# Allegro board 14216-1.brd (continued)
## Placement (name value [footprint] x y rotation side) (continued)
C8006  SC1U6D3V3KX-2GP  [C603H36]  200.97 141.05 90 top
C8007  SC1U6D3V3KX-2GP  [C603H36]  200.9 139.79 270 bottom
C8008  SC1U6D3V3KX-2GP  [C603H36]  200.93 151.95 90 top
C8009  SC1U6D3V3KX-2GP  [C603H36]  200.94 150.6 90 top
C8010  SCD1U16V2KX-3GP  [C402H22]  201.13 136.6 270 bottom
C8011  SCD1U16V2KX-3GP  [C402H22]  169.76 174.17 0 bottom
C8012  SCD1U16V2KX-3GP  [C402H22]  200.93 152.44 270 bottom
C8013  SCD1U16V2KX-3GP  [C402H22]  151.75 165.94 90 bottom
C8014  SC1U6D3V3KX-2GP  [C603H36]  200.94 147.92 90 top
C8015  SC1U6D3V3KX-2GP  [C603H36]  200.97 142.39 90 top
C8016  SC1U6D3V3KX-2GP  [C603H36]  200.94 153.29 90 top
C8017  SCD1U16V2KX-3GP  [C402H22]  183.12 143.86 270 bottom
C8018  SCD1U16V2KX-3GP  [C402H22]  158.24 173.13 0 bottom
C8019  SCD1U16V2KX-3GP  [C402H22]  188.26 143.87 90 bottom
C8020  SCD1U16V2KX-3GP  [C402H22]  198.28 140.52 90 bottom
C8101  SCD1U16V2KX-3GP  [C402H22]  185.94 173.4 180 top
C8102  SCD1U16V2KX-3GP  [C402H22]  180.83 169.8 270 bottom
C8103  SC1U6D3V3KX-2GP  [C603H36]  157.1 172.57 180 top
C8104  SCD1U16V2KX-3GP  [C402H22]  166.22 157.08 0 top
C8105  SCD1U16V2KX-3GP  [C402H22]  174.71 174.1 0 bottom
C8106  SC1U6D3V3KX-2GP  [C603H36]  188.33 173.83 180 top
C8107  SC1U6D3V3KX-2GP  [C603H36]  189.62 173.84 180 top
C8108  SC1U6D3V3KX-2GP  [C603H36]  175.04 173.62 180 top
C8109  SC1U6D3V3KX-2GP  [C603H36]  184.04 173.61 180 top
C8110  SCD1U16V2KX-3GP  [C402H22]  151.62 169.98 270 top
C8111  SCD1U16V2KX-3GP  [C402H22]  166.22 158.75 180 top
C8112  SCD1U16V2KX-3GP  [C402H22]  177.52 173.66 180 top
C8113  SCD1U16V2KX-3GP  [C402H22]  155.52 173.13 0 bottom
C8114  SC1U6D3V3KX-2GP  [C603H36]  176.42 173.63 180 top
C8115  SC1U6D3V3KX-2GP  [C603H36]  155.78 172.57 180 top
C8116  SC1U6D3V3KX-2GP  [C603H36]  151.52 162.06 90 bottom
C8117  SCD1U16V2KX-3GP  [C402H22]  176.61 174.15 0 bottom
C8118  SCD1U16V2KX-3GP  [C402H22]  151.78 169.61 90 bottom
C8119  SCD1U16V2KX-3GP  [C402H22]  151.77 170.46 90 bottom
C8120  SCD1U16V2KX-3GP  [C402H22]  180.85 171.08 270 bottom
C8301  SCD01U50V2KX-1GP  [C402H22]  142.67 133.14 270 top
C8302  SC1U10V2KX-1GP  [C402H22]  146.16 140.24 180 top
C8303  SCD1U16V2KX-3GP  [C402H22]  144.58 137.75 270 bottom
C8304  SC1U10V2KX-1GP  [C402H22]  146.67 134.78 90 top
C8305  SC470P50V2KX-3GP  [C402H22]  148.83 136.94 90 bottom
C8306  SCD1U16V2KX-3GP  [C402H22]  151.24 148.48 180 bottom
C8307  SC10U10V5KX-2GP  [C805H54]  147.81 132.62 270 top
C8308  SCD1U16V2KX-3GP  [C402H22]  149.75 134.08 90 top
C8309  SCD1U16V2KX-3GP  [C402H22]  144.22 138.24 0 top
C8310  SC10U10V5KX-2GP  [C805H54]  148.19 140.36 270 top
C8311  SCD1U16V2KX-3GP  [C402H22]  146.24 133.94 90 top
C8316  SC2200P50V2KX-2GP  [C402H22]  148.83 137.82 90 bottom
C9602  SCD1U16V2KX-3GP  [C402H22]  166.48 86.68 270 top
CARD1  CARDBUS11P-SKT-8-GP  [CS1S-461HN]  22.1 16.87 270 top
CN6301  PTWO-CON24-7-GP  [196547-24031-3]  194.45 33.27 90 top
CPU1  HASWELL-6-GP-U  [BGA1168M4024H64]  117.8 83.77 0 bottom
D2001  RB751V-40H-GP  [SOD323AKH38]  149.02 80.12 270 top
D2401  RB751V-40-H-GP  [SOD323AKH40]  188.2 67.11 90 bottom
D2501  BAS40C-2-GP  [SOT-23-9H44]  30.14 11.71 90 top
D2601  RB551V30-GP  [SOD323AKH38]  100.29 141.48 90 bottom
D2701  BAT54C-7-F-3-GP  [SOT23-2D4-312H48]  174.32 24.68 0 bottom
D3602  BAS16-6-GP  [SOT23-2D4-312H44]  164.95 63.3 270 top
D4301  LBAV99LT1G-1-GP  [SOT23-2D4-312H44]  187.65 177.88 0 top
D4302  LBAV99LT1G-1-GP  [SOT23-2D4-312H44]  174.76 177.72 0 top
D4303  LBAV99LT1G-1-GP  [SOT23-2D4-312H44]  183.66 177.88 0 top
D5201  BAT54C-7-F-3-GP  [SOT23-2D4-312H48]  69.17 161.68 270 bottom
D5202  BAT54C-7-F-3-GP  [SOT23-2D4-312H48]  61.56 165.37 0 top
D5401  BAW56-5-GP  [SOT-23-9H44]  40.55 79.02 90 bottom
D5501  RB551V30-GP  [SOD323AKH38]  31.91 70.36 270 top
D7301  BAT54A-1-GP  [SOT23-2D4-312H44]  154.66 124.41 180 bottom
D7601  1SS400GPT-GP  [SOD723AKH27]  172.45 127.41 270 top
D7602  1SS400GPT-GP  [SOD723AKH27]  172.45 126.13 270 top
D8301  BAT54C-7-F-3-GP  [SOT23-2D4-312H48]  167.61 53.76 90 top
DB1  PAD-10P-177042-GP  [PAD-10P-177042]  170.29 30.76 180 bottom
DCIN1  ACES-CON6-63-GP  [50458-00601-W01]  92.8 166.77 180 top
DM1  DDR3-204P-108-GP-U  [80001-1921]  92.3 34.07 180 bottom
DM2  DDR3-204P-259-GP  [AS0A621-J4SB-7H]  126.8 20.87 0 bottom
EC401  SCD1U16V2KX-3GP  [C402H22]  92.88 97.78 90 bottom
EC402  SCD1U16V2KX-3GP  [C402H22]  101.2 94.14 180 top
EC701  SCD1U16V2KX-3GP  [C402H22]  97.58 100.22 90 bottom
EC702  SCD1U16V2KX-3GP  [C402H22]  95.68 99.36 90 bottom
EC1501  SC1KP50V2KX-1GP  [C402H22]  144.39 100.83 90 top
EC1502  SC1KP50V2KX-1GP  [C402H22]  149.87 91.3 270 bottom
EC1701  SC4D7P50V2BN-GP  [C402H22]  150.73 84.61 90 bottom
EC1702  SC1KP50V2KX-1GP  [C402H22]  171.04 83.6 270 bottom
EC1703  SC1KP50V2KX-1GP  [C402H22]  149.83 93.02 90 bottom
EC1704  SC1KP50V2KX-1GP  [C402H22]  139.26 55.99 0 bottom
EC1705  SC1KP50V2KX-1GP  [C402H22]  143.01 52.79 270 bottom
EC1706  SC1KP50V2KX-1GP  [C402H22]  166.48 85.8 270 top
EC1707  SCD1U16V2KX-3GP  [C402H22]  168.77 80.5 90 top
EC1801  SC10P50V2JN-4GP  [C402H22]  127.97 62.67 0 top
EC1901  SC10P50V2JN-4GP  [C402H22]  138.42 62.69 0 bottom
EC1902  SCD1U16V2KX-3GP  [C402H22]  139.24 62.69 180 bottom
EC1903  SCD1U16V2KX-3GP  [C402H22]  143.82 62.69 0 top
EC2501  SC4D7P50V2BN-GP  [C402H22]  145.93 52.36 180 bottom
EC2502  SC4D7P50V2BN-GP  [C402H22]  157.41 51.62 180 bottom
EC2503  SC10P50V2JN-4GP  [C402H22]  145.93 54.14 0 bottom
EC2601  SCD1U16V2KX-3GP  [C402H22]  100.03 137.67 270 bottom
EC2602  SC10P50V2JN-4GP  [C402H22]  96.15 141.03 90 bottom
EC2701  SC10P50V2JN-4GP  [C402H22]  177.3 12.4 90 bottom
EC2703  SCD1U25V2KX-GP  [C402H22]  185.61 7.94 90 bottom
EC2704  SC1KP50V2KX-1GP  [C402H22]  189.9 12.39 90 bottom
EC2705  SC1KP50V2KX-1GP  [C402H22]  189.47 9.55 180 bottom
EC2706  SC1KP50V2KX-1GP  [C402H22]  192.26 14.56 270 bottom
EC2707  SC1KP50V2KX-1GP  [C402H22]  190.43 9.58 180 bottom
EC2708  SCD1U16V2KX-3GP  [C402H22]  174.66 15.53 90 bottom
EC2709  SCD1U16V2KX-3GP  [C402H22]  175.68 16.34 90 bottom
EC2901  SC1KP50V2KX-1GP  [C402H22]  90.64 4.68 0 top
EC2902  SC1KP50V2KX-1GP  [C402H22]  91.76 7.07 180 top
EC2903  SC1KP50V2KX-1GP  [C402H22]  90.38 8.31 0 top
EC2904  SC1KP50V2KX-1GP  [C402H22]  90.43 11.28 180 top
EC2905  SC100P50V2JN-3GP  [C402H22]  182.1 23.4 90 bottom
EC2906  SC100P50V2JN-3GP  [C402H22]  183.88 23.4 270 bottom
EC2907  SC100P50V2JN-3GP  [C402H22]  192.13 16.41 270 bottom
EC2908  SC100P50V2JN-3GP  [C402H22]  181.39 27 180 top
EC3101  SC10P50V2JN-4GP  [C402H22]  39.35 171.62 0 bottom
EC3102  SC10P50V2JN-4GP  [C402H22]  39.35 173.4 180 bottom
EC3103  SC10P50V2JN-4GP  [C402H22]  39.35 175.1 0 bottom
EC3104  SC10P50V2JN-4GP  [C402H22]  39.35 176.88 180 bottom
EC3105  SC10P50V2JN-4GP  [C402H22]  39.35 171.62 180 top
EC3106  SC10P50V2JN-4GP  [C402H22]  39.35 173.4 0 top
EC3107  SC10P50V2JN-4GP  [C402H22]  39.35 175.1 180 top
EC3108  SC10P50V2JN-4GP  [C402H22]  39.35 176.88 0 top
EC3201  SC10P50V2JN-4GP  [C402H22]  29.6 21.14 90 top
EC3301  SC4D7P50V2BN-GP  [C402H22]  29.52 24.87 90 top
EC3302  SC4D7P50V2BN-GP  [C402H22]  30.06 14.12 90 top
EC3303  SC4D7P50V2BN-GP  [C402H22]  29.99 15.22 90 top
EC3304  SC4D7P50V2BN-GP  [C402H22]  29.95 16.34 90 top
EC3305  SC4D7P50V2BN-GP  [C402H22]  29.57 27.16 90 top
EC3306  SC4D7P50V2BN-GP  [C402H22]  29.59 23.49 90 top
EC3307  SC4D7P50V2BN-GP  [C402H22]  29.57 28.6 90 top
EC4201  SC10U25V5KX-GP  [C805H56]  92.67 159.64 90 top
EC4202  SCD1U25V2KX-GP  [C402H22]  92.54 158.25 90 top
EC4301  SC10P50V2JN-4GP  [C402H22]  186.55 175.38 90 top
EC4302  SC10P50V2JN-4GP  [C402H22]  184.74 175.37 270 top
EC4303  SCD1U25V2KX-GP  [C402H22]  152.17 173.1 0 top
EC4304  SCD1U50V3KX-GP  [C603H36]  151.03 173.18 0 top
EC4305  SC15P50V2JN-2-GP  [C402H22]  176.05 175.27 270 top
EC4401  SC2200P50V2KX-2GP  [C402H22]  120.3 159.59 180 top
EC4402  SCD1U25V2KX-GP  [C402H22]  120.3 159.59 0 bottom
EC4601  SCD1U50V3KX-GP  [C603H36]  78.71 16.88 0 top
EC4701  SCD1U25V2KX-GP  [C402H22]  103.18 104.6 90 bottom
EC5205  SC6D8P50V2DN-GP  [C402H22]  82.15 166.72 180 top
EC5206  SC22P50V2JN-4GP  [C402H22]  81.29 166.73 180 top
EC5210  SC33P50V2JN-3GP  [C402H22]  82.86 158.65 180 bottom
EC5801  SC33P50V2JN-3GP  [C402H22]  168.16 65.77 270 bottom
EC5802  SC33P50V2JN-3GP  [C402H22]  166.41 65.76 90 bottom
EC6101  SC1KP50V2KX-1GP  [C402H22]  191.19 174.19 270 top
EC6102  SC220P50V2KX-3GP  [C402H22]  31.9 4.56 90 top
EC6103  SC220P50V2KX-3GP  [C402H22]  35.72 4.54 90 top
EC6104  SCD1U16V2KX-3GP  [C402H22]  39.55 3.73 90 top
EC6105  SCD1U16V2KX-3GP  [C402H22]  191.15 177.61 270 top
EC6201  SC33P50V2JN-3GP  [C402H22]  54.67 78.63 180 top
EC6202  SC33P50V2JN-3GP  [C402H22]  54.67 76.86 0 top
EC6203  SC33P50V2JN-3GP  [C402H22]  51.68 72.42 90 top
EC6204  SC33P50V2JN-3GP  [C402H22]  49.99 72.42 270 top
EC6205  SC33P50V2JN-3GP  [C402H22]  46.08 73.4 0 top
EC6206  SC33P50V2JN-3GP  [C402H22]  46.08 75.18 180 top
EC6207  SCD1U16V2KX-3GP  [C402H22]  190.01 125.99 180 top
EC6208  SCD1U16V2KX-3GP  [C402H22]  188.7 122.38 180 top
EC9701  SCD1U25V2KX-GP  [C402H22]  86.01 85.7 90 top
EC9702  SC1KP50V2KX-1GP  [C402H22]  113.91 153.28 0 bottom
EC9703  SCD1U25V2KX-GP  [C402H22]  64.94 64.96 180 top
EC9704  SCD1U25V2KX-GP  [C402H22]  137.8 155.4 90 top
EC9705  SCD1U25V2KX-GP  [C402H22]  57.12 56.64 0 top
EC9706  SCD1U25V2KX-GP  [C402H22]  54.21 32.67 270 top
EC9707  SCD1U25V2KX-GP  [C402H22]  110.73 129.82 180 bottom
EC9708  SC1KP50V2KX-1GP  [C402H22]  121.84 148.31 0 top
EC9709  SC1KP50V2KX-1GP  [C402H22]  33.27 55.49 270 bottom
EC9710  SC1KP50V2KX-1GP  [C402H22]  123.73 146.41 180 bottom
EC9711  SC1KP50V2KX-1GP  [C402H22]  102.07 135.34 90 bottom
EC9712  SCD1U25V2KX-GP  [C402H22]  141.87 148.36 90 top
EC9713  SCD1U25V2KX-GP  [C402H22]  68.82 27.06 90 top
EC9714  SC1KP50V2KX-1GP  [C402H22]  137.78 155.06 270 bottom
EC9715  SC1KP50V2KX-1GP  [C402H22]  141.11 121.46 270 top
EC9716  SC1KP50V2KX-1GP  [C402H22]  135.68 127.85 270 top
EC9717  SC1KP50V2KX-1GP  [C402H22]  154.92 113.64 90 top
EC9718  SC1U10V2KX-1GP  [C402H22]  20.94 32.82 180 bottom
EC9719  SC1U10V2KX-1GP  [C402H22]  196.97 17.69 270 top
EC9720  SC1U10V2KX-1GP  [C402H22]  197.72 38.54 180 bottom
EC9721  SC1U10V2KX-1GP  [C402H22]  44.25 16.51 180 top
EC9722  SC1U10V2KX-1GP  [C402H22]  174.83 8.26 180 bottom
EC9723  SC1U10V2KX-1GP  [C402H22]  73.13 157.81 90 bottom
EC9724  SC1U10V2KX-1GP  [C402H22]  35.05 70.16 90 top
EC9725  SC1U10V2KX-1GP  [C402H22]  196.25 129.99 270 top
EC9726  SC1U10V2KX-1GP  [C402H22]  191.64 55.17 180 top
EC9727  SC1U10V2KX-1GP  [C402H22]  156.17 38.03 0 top
EC9728  SC1U10V2KX-1GP  [C402H22]  201.29 146.85 90 top
EC9729  SC1U10V2KX-1GP  [C402H22]  154.67 172.72 180 top
EC9730  SC1U10V2KX-1GP  [C402H22]  152.16 161.95 180 top
EC9731  SC1U10V2KX-1GP  [C402H22]  181.59 173.79 180 top
EC9732  SC1U10V2KX-1GP  [C402H22]  193.66 7.79 0 bottom
EC9733  SC1U10V2KX-1GP  [C402H22]  61.2 10.42 90 bottom
EC9734  SC1U10V2KX-1GP  [C402H22]  45.2 18.5 0 top
EC9735  SC1U10V2KX-1GP  [C402H22]  60.18 66.83 270 top
EC9736  SC1U10V2KX-1GP  [C402H22]  60.23 66.8 90 bottom
EC9737  SC1U10V2KX-1GP  [C402H22]  38.23 13.01 90 top
EC9738  SC1U10V2KX-1GP  [C402H22]  87.61 152.15 270 bottom
EC9739  SC1KP50V2KX-1GP  [C402H22]  188.75 14.05 0 top
EC9740  SC1KP50V2KX-1GP  [C402H22]  109.51 140.24 270 bottom
EC9741  SC1KP50V2KX-1GP  [C402H22]  162.89 91.68 90 top
EC9742  SCD1U25V2KX-GP  [C402H22]  156.8 117.21 270 bottom
EC9743  SC1KP50V2KX-1GP  [C402H22]  178.71 26.1 90 bottom
EC9744  SC1KP50V2KX-1GP  [C402H22]  179.99 19.81 270 top
EC9745  SC1KP50V2KX-1GP  [C402H22]  184.51 13.77 180 top
EC9746  SCD1U25V2KX-GP  [C402H22]  201.04 134.12 270 bottom
EC9747  SC1KP50V2KX-1GP  [C402H22]  121.14 146.21 180 bottom
EC9748  SC1KP50V2KX-1GP  [C402H22]  99.93 105.44 90 top
EC9749  SCD1U25V2KX-GP  [C402H22]  144.64 127.59 270 top
EC9750  SCD1U25V2KX-GP  [C402H22]  201.02 135.03 270 bottom
EC9751  SCD1U25V2KX-GP  [C402H22]  194.01 84.71 90 bottom
EC9752  SCD1U25V2KX-GP  [C402H22]  193.06 90.5 90 bottom
EC9753  SCD1U25V2KX-GP  [C402H22]  193.43 89.59 90 bottom
EC9754  SCD1U25V2KX-GP  [C402H22]  201.05 133.23 270 bottom
EC9755  SCD1U25V2KX-GP  [C402H22]  178.02 121.71 90 bottom
EC9756  SCD1U25V2KX-GP  [C402H22]  180.04 119.8 90 bottom
EC9757  SCD1U25V2KX-GP  [C402H22]  163.22 121.66 180 bottom
EC9758  SCD1U25V2KX-GP  [C402H22]  168.16 175.1 270 bottom
EC9759  SCD1U25V2KX-GP  [C402H22]  148.94 172.4 180 bottom
EC9760  SCD1U25V2KX-GP  [C402H22]  141.78 178.34 0 bottom
EC9761  SCD1U25V2KX-GP  [C402H22]  134.43 173.06 90 bottom
ED6101  AZ5725-01FDR7G-GP  [SOD882-10D6-1H20]  191.16 175.07 270 top
EL4201  0R0805-PAD-1-GP-U  [0R0805-PAD-U]  92.56 156.47 90 top
EL4202  0R0805-PAD-1-GP-U  [0R0805-PAD-U]  92.55 154.53 90 top
EL4203  0R0805-PAD-1-GP-U  [0R0805-PAD-U]  100.7 159.03 90 top
EL4204  0R0805-PAD-1-GP-U  [0R0805-PAD-U]  100.67 160.88 90 top
EU401  ESD105-B1-02EL-GP  [TVS10D6-D3D5-1H13]  131.3 62.39 90 bottom
EU3101  TVWDF1004AD0-1-GP  [DFN10G2510H26]  37.21 174.12 270 bottom
EU3102  TVWDF1004AD0-1-GP  [DFN10G2510H26]  37.21 174.12 270 top
EU3403  AZC099-04S-1-GP  [SOT-6H58]  20.72 38.07 270 top
EU3404  AZC099-04S-1-GP  [SOT-6H58]  187.87 39.42 270 bottom
EU5602  AZ1045-04F-R7G-GP  [DFN10G2510H26]  185.4 33.63 270 bottom
F5201  POLYSW-1D1A24V-2-GP  [POLYSW-4633-UH63]  95.94 151.44 90 bottom
F5203  POLYSW-D5A6V-1-GP  [POLYSW-2114H50]  73.51 161.19 0 bottom
F5501  POLYSW-1D1A6V-9-GP-U  [POLYSW-2114H30]  20.73 69.86 90 top
F6201  POLYSW-D5A6V-1-GP  [POLYSW-2114H50]  187.3 122.94 90 bottom
FAN1  ETY-CON3-8-GP  [3703K-Q03N-11L]  91.38 140.62 24.9 bottom
FAN261  AP2113MTR-G1-GP  [SOIC8H69]  100.13 145.61 90 bottom
G1901  GAP-OPEN  [CON2O-U]  145.85 61.7 270 bottom
G6101  GAP-OPEN  [CON2O-U]  192.96 173.32 0 top
G6102  GAP-OPEN  [CON2O-U]  191.02 175.85 180 bottom
GPU1  N14M-GE-S-A2-GP  [BGA595M23H83]  166.15 140.17 90 bottom
H1  HOLE256R126-1-GP  [HOLE256R126]  141.7 165.77 0 top
H2  HOLE335R115-GP  [HOLE335R115]  169.3 12.77 0 top
H3  HOLE335R115-GP  [HOLE335R115]  20.3 50.77 0 top
H4  HOLE335R115-GP  [HOLE335R115]  96.3 128.47 0 top
H5  HOLE335R115-GP  [HOLE335R115]  37.4 164.77 0 top
H6  HOLE256R126-1-GP  [HOLE256R126]  199.5 56.27 0 top
H7  HOLE296R182-GP  [HOLE296R182]  153.9 60.97 0 top
HCPU1  HOLE197R166-1-GP  [HOLE197R166]  90.6 70.77 0 top
HCPU2  HOLE197R166-1-GP  [HOLE197R166]  145 70.77 0 top
HCPU3  HOLE197R166-1-GP  [HOLE197R166]  117.8 102.77 0 top
HDA27  ALC3234-CG-GP  [QFN48J6-G465H40]  183.22 16.29 270 bottom
HDD1  STAR-CON12-1-GP  [132F12-010000-A2-R]  194.3 30.88 270 bottom
HDLED1  LED-W-27-GP-U  [LED3015-1A2K-3PH44]  22.7 1.47 90 top
HDMI1  PAD-D-SUB-HDMI-COLAY-GP-U  [PAD-D-SUB-HDMI-COLAY-U]  4.15 65.22 90 bottom
HGPU1  STF237R117H81-1-GP  [STF237R117H81]  149.2 157.37 0 bottom
HGPU2  STF237R117H81-1-GP  [STF237R117H81]  200.9 114.27 0 bottom
HGPU3  STF237R117H81-1-GP  [STF237R117H81]  200.5 158.67 180 bottom
KB1  ACES-CON30-10-GP  [FL4S030HT6R300-DT]  186.85 104.55 270 top
KB_BL1  ACES-CON4-56-GP-U  [51575-00401-W01]  196.2 123.07 90 top
KBC24  NPCE285PA0DX-GP  [LQFP128H63]  185 74.99 270 top
L1101  0R3J-0-U-GP  [R603H22]  132.27 106.52 90 bottom
L1102  0R3J-0-U-GP  [R603H22]  135.13 106.59 270 bottom
L1103  IND-2D2UH-196-GP  [L603H40]  131.74 106.57 0 top
L1104  IND-2D2UH-196-GP  [L603H40]  130.38 106.34 0 top
L3001  IND-4D7UH-242-GP  [L2520-D820H41]  53.21 174.73 180 top
L5501  BLM18BB220SN-GP  [L1608-UH38]  21.15 61.9 270 top
L5502  BLM18BB220SN-GP  [L1608-UH38]  21.2 64.05 270 top
L5503  BLM18BB220SN-GP  [L1608-UH38]  21.09 59.18 270 top
L7301  MHC1608S121PBP-GP  [L603H38]  160 139.08 0 top
L7501  MHC1608S300QBP-GP  [L603H38]  161.39 144.56 270 top
L7601  MHC1608S300QBP-GP  [L603H38]  170.14 129.65 180 top
L7602  MCB1608S181FBP-GP  [L603H38]  168.26 129.7 270 top
LCD1  ACES-CON40-18-GP  [51540-04001-W01]  75.3 167.07 270 top
LED1  LED-OW-8-GP  [LED3020-3P-6H44]  17.7 1.77 180 top
LOM30  RTL8111G-CGT-1-GP-U2  [QFN32J4-G2D85H36]  48.93 168.97 90 top
NOREF  -  [unnamed]  203.92 74.02 0 top
NOREF#2  -  [unnamed]  3.34 7.58 0 top
NOREF#3  -  [#2]  -49.22 -5.53 0 top
NOREF#4  -  [#2]  4.3 -48.23 0 top
NOREF#5  -  [#2]  110.42 56.77 0 top
NOREF#6  *  [unnamed]  71.51 28.5 0 top
NOREF#7  *  [unnamed]  200.9 50.96 0 top
NOREF#8  -  [#2]  196.3 5.01 0 top
NOREF#9  -  [#2]  2.65 126.01 90 top
NOREF#10  -  [#2]  4.3 -48.23 0 top
NOREF#11  *  [unnamed]  169.68 86.67 0 top
NOREF#12  -  [#2]  149.46 10.32 0 top
NOREF#13  *  [unnamed]  4.03 2.99 0 top
NOREF#14  *  [unnamed]  201.01 4.74 0 top
NOREF#15  *  [unnamed]  33.48 177.12 0 top
NOREF#16  -  [unnamed]  -3.72 178.69 0 top
NOREF#17  -  [unnamed]  205.45 184.19 0 top
NOREF#18  *  [unnamed]  0.5 156.41 0 top
NOREF#19  -  [#2]  -8.05 133.14 0 top
NOREF#20  -  [unnamed]  80.02 122.56 0 top
NOREF#21  -  [unnamed]  5.79 79.07 270 top
NOREF#22  *  [unnamed]  201.78 176.85 0 top
NOREF#23  -  [unnamed]  206 4.12 0 top
NOREF#24  -  [unnamed]  148.1 163.97 0 top
NOREF#25  *  [unnamed]  43.72 11.28 0 top
NOREF#26  -  [unnamed]  0.11 16.95 0 top
NOREF#27  -  [#2]  125.19 190.37 180 top
NOREF#28  -  [unnamed]  111.85 187.26 0 top
NOREF#29  *  [unnamed]  15.62 79.19 0 top
NOREF#30  -  [#2]  4.3 -48.23 0 top
NOREF#31  *  [unnamed]  200.4 184.34 0 top
NOREF#32  *  [unnamed]  201.78 176.85 180 bottom
NOREF#33  -  [#2]  125.19 190.37 0 bottom
NOREF#34  *  [unnamed]  150.44 119.23 180 bottom
NOREF#35  *  [unnamed]  200.4 184.34 180 bottom
NOREF#36  *  [unnamed]  201.01 4.74 180 bottom
NOREF#37  *  [unnamed]  0.5 156.41 180 bottom
NOREF#38  *  [unnamed]  150.71 45.57 180 bottom
NOREF#39  *  [unnamed]  15.62 79.19 180 bottom
NOREF#40  *  [unnamed]  4.03 2.99 180 bottom
NOREF#41  -  [#2]  107 0 180 bottom
NOREF#42  -  [#2]  2.65 140.49 270 bottom
NOREF#43  -  [#2]  77.99 71.92 180 bottom
NOREF#44  -  [#2]  196.72 177.44 180 bottom
NOREF#45  -  [#2]  33.99 96.98 180 bottom
ODD1  ACES-CON20-30-GP-U  [51519-02001-W03]  159.3 81.32 90 top
PC4010  SCD47U25V3KX-1GP  [C603H36]  113.49 158.45 180 bottom
PC4201  SC1U25V3KX-1-GP  [C603H36]  96.12 150.02 90 top
PC4202  SCD1U50V3KX-GP  [C603H36]  117.38 176.07 90 top
PC4203  SCD01U50V2KX-1GP  [C402H22]  104.2 153.37 90 top
PC4204  SCD01U50V2KX-1GP  [C402H22]  104.2 155.15 90 top
PC4205  SCD01U50V2KX-1GP  [C402H22]  104.2 154.26 90 top
PC4206  SC10U25V5KX-GP  [C805H56]  104.86 156.65 90 top
PC4401  SC560P50V-GP  [C603]  122.62 160.56 270 top
PC4402  SCD1U25V2KX-GP  [C402H22]  110.1 156.51 90 top
PC4403  SC1U25V3KX-1-GP  [C603H36]  111.37 157.58 90 top
PC4404  SC1U25V3KX-1-GP  [C603H36]  108.96 157.58 270 top
PC4406  SC10U25V5KX-GP  [C805H56]  117.51 159.59 0 bottom
PC4407  SC1U25V3KX-1-GP  [C603H36]  115.78 162.56 0 bottom
PC4408  SC4D7U25V5KX-GP  [C805H54]  118.9 159.59 180 top
PC4409  SCD1U50V3KX-GP  [C603H36]  119.18 159.59 0 bottom
PC4411  SCD047U25V2KX-GP  [C402H22]  111.82 159.91 90 top
PC4412  SCD01U50V2KX-1GP  [C402H22]  107.96 160.61 90 top
PC4413  SC3300P50V3KX-1GP  [C603H36]  114.18 161.37 180 top
PC4415  SC10U25V5KX-GP  [C805H56]  133.15 168.46 270 top
PC4416  SC10U25V5KX-GP  [C805H56]  142.97 158.49 90 top
PC4417  SC10U25V5KX-GP  [C805H56]  133.15 166.55 270 top
PC4418  SC10U25V5KX-GP  [C805H56]  133.15 164.65 270 top
PC4419  SCD1U50V3KX-GP  [C603H36]  143.07 160.04 90 top
PC4420  SCD1U25V2KX-GP  [C402H22]  109.46 165.16 0 top
PC4421  SCD1U25V2KX-GP  [C402H22]  109.05 166.43 270 top
PC4422  SC220P50V2JN-3GP  [C402H22]  107.96 161.5 90 top
PC4423  SCD1U25V2KX-GP  [C402H22]  108.62 165.16 0 top
PC4424  SCD1U25V2KX-GP  [C402H22]  126.26 167.6 0 top
PC4425  SCD01U50V2KX-1GP  [C402H22]  113.55 155.02 180 bottom
PC4426  SC10U25V5KX-GP  [C805H56]  117 159.59 180 top
PC4427  SC1U25V3KX-1-GP  [C603H36]  125.61 170.57 0 top
PC4431  SC1U25V3KX-1-GP  [C603H36]  120.63 168.94 180 top
PC4433  SCD47U6D3V2KX-1-GP  [C402H22]  112.64 168.46 270 top
PC4434  SC1U25V3KX-1-GP  [C603H36]  104.83 174.38 270 top
PC4509  SC4D7U25V5KX-GP  [C805H54]  34.81 49.55 90 top
PC4514  SCD1U50V3KX-GP  [C603H36]  47.35 57.17 90 top
PC4515  SCD1U50V3KX-GP  [C603H36]  50.15 53.24 0 bottom
PC4516  SCD1U50V3KX-GP  [C603H36]  46.46 54.89 270 top
PC4517  SCD1U16V2KX-3GP  [C402H22]  31.38 27.58 90 bottom
PC4518  SCD1U16V2KX-3GP  [C402H22]  48.27 27.45 270 bottom
PC4519  SC10U25V5KX-GP  [C805H56]  39 50.82 270 top
PC4520  SC330P50V3KX-GP  [C603]  40.14 45.87 180 top
PC4521  SC1KP50V2KX-1GP  [C402H22]  46.16 56 90 top
PC4522  SC18P50V2JN-1-GP  [C402H22]  42.53 58.77 270 top
PC4523  SC18P50V2JN-1-GP  [C402H22]  38.11 59.94 0 top
PC4524  SC1U6D3V3KX-2GP  [C603H36]  41.99 50.62 0 top
PC4525  SCD1U50V3KX-GP  [C603H36]  34.78 47.9 90 top
PC4526  SC4D7U6D3V3KX-GP  [C603H36]  41.31 59.61 90 bottom
PC4527  SC10U25V5KX-GP  [C805H56]  47.51 49.3 270 top
PC4528  SC10U25V5KX-GP  [C805H56]  34.81 49.55 270 bottom
PC4529  SC4D7U25V5KX-GP  [C805H54]  47.51 49.3 90 bottom
PC4530  SCD1U50V3KX-GP  [C603H36]  47.48 47.65 270 top
PC4531  SCD01U50V2KX-1GP  [C402H22]  40.9 50.95 0 top
PC4532  SCD1U50V3KX-GP  [C603H36]  47.35 58.44 90 top
PC4533  SC1U25V3KX-1-GP  [C603H36]  50.02 59.59 270 bottom
PC4534  SCD1U50V3KX-GP  [C603H36]  43.67 58.32 90 bottom
PC4535  SCD1U50V3KX-GP  [C603H36]  36.3 54.38 90 top
PC4536  SC560P50V-GP  [C603]  42.17 45.87 180 top
PC4601  SCD1U16V2KX-3GP  [C402H22]  111.84 144.02 0 top
PC4604  SC1U25V3KX-1-GP  [C603H36]  115.58 136.34 0 top
PC4606  SCD1U16V2KX-3GP  [C402H22]  121.82 143.77 90 bottom
PC4609  SC1KP50V2KX-1GP  [C402H22]  116.6 142.94 0 bottom
PC4610  SCD1U16V2KX-3GP  [C402H22]  115.58 142.94 180 bottom
PC4611  SC6K8P50V2KX-GP  [C402H22]  114.66 140.62 180 bottom
PC4612  SC1KP50V2KX-1GP  [C402H22]  113.43 142.3 0 top
PC4613  SC1KP50V2KX-1GP  [C402H22]  110.68 142.96 180 top
PC4701  SC10U25V5KX-GP  [C805H56]  118.07 132.26 90 top
PC4702  SC10U25V5KX-GP  [C805H56]  118.07 130.35 90 top
PC4703  SC10U25V5KX-GP  [C805H56]  118.17 134.24 270 bottom
PC4704  SCD1U50V3KX-GP  [C603H36]  118.22 132.59 270 bottom
PC4706  SCD22U25V3KX-GP  [C603H40]  118.12 136.34 180 top
PC4707  SCD047U25V2KX-GP  [C402H22]  112.25 138.46 270 top
PC4708  SCD1U16V2KX-3GP  [C402H22]  112.23 139.28 270 top
PC4709  SCD1U16V2KX-3GP  [C402H22]  110.84 140.5 180 top
PC4710  SCD1U25V2KX-GP  [C402H22]  110.97 138.78 0 top
PC4717  SC22U6D3V5MX-2GP  [C805H58]  103.23 102.2 270 top
PC4718  SC22U6D3V5MX-2GP  [C805H58]  103.23 111.66 90 bottom
PC4719  SC22U6D3V5MX-2GP  [C805H58]  109.69 85.24 90 top
PC4720  SC22U6D3V5MX-2GP  [C805H58]  118.03 115.09 90 top
PC4721  SC22U6D3V5MX-2GP  [C805H58]  115.98 88.52 0 top
PC4722  SC22U6D3V5MX-2GP  [C805H58]  103.23 115.47 270 top
PC4723  SC22U6D3V5MX-2GP  [C805H58]  118.05 111.03 270 bottom
PC4724  SC22U6D3V5MX-2GP  [C805H58]  119.64 88.52 0 top
PC4725  SC22U6D3V5MX-2GP  [C805H58]  118 113.2 90 top
PC4726  SC22U6D3V5MX-2GP  [C805H58]  103.23 109.76 90 bottom
PC4727  SC22U6D3V5MX-2GP  [C805H58]  103.23 105.95 270 top
PC4728  SC22U6D3V5MX-2GP  [C805H58]  103.23 109.76 270 top
PC4729  SC22U6D3V5MX-2GP  [C805H58]  103.23 113.57 270 top
PC4730  SC22U6D3V5MX-2GP  [C805H58]  117.81 88.52 0 top
PC4731  SC22U6D3V5MX-2GP  [C805H58]  110.5 88.52 0 top
PC4732  SC22U6D3V5MX-2GP  [C805H58]  118.05 109.2 270 bottom
PC4733  SC22U6D3V5MX-2GP  [C805H58]  103.23 104.04 270 top
PC4734  SC22U6D3V5MX-2GP  [C805H58]  112.33 88.52 0 top
PC4735  SC22U6D3V5MX-2GP  [C805H58]  103.23 111.66 270 top
PC4736  SC22U6D3V5MX-2GP  [C805H58]  114.15 88.52 0 top
PC4737  SC22U6D3V5MX-2GP  [C805H58]  103.23 107.85 270 top
PC4739  SC22U6D3V5MX-2GP  [C805H58]  118 111.3 90 top
PC4740  SC22U6D3V5MX-2GP  [C805H58]  103.23 105.95 90 bottom
PC4741  SC22U6D3V5MX-2GP  [C805H58]  109.69 83.33 90 top
PC4742  SC22U6D3V5MX-2GP  [C805H58]  118.03 117 90 top
PC4744  SC22U6D3V5MX-2GP  [C805H58]  103.23 107.85 90 bottom
PC4814  SC4D7U25V5KX-GP  [C805H54]  131.74 138.58 270 top
PC4815  SC1U10V2KX-1GP  [C402H22]  128.17 140.48 0 top
PC4821  SC1KP50V2KX-1GP  [C402H22]  130.06 147.47 270 top
PC4822  SCD1U50V3KX-GP  [C603H36]  129.88 140.16 90 top
PC4823  SC18P50V2JN-1-GP  [C402H22]  127.87 147.47 0 top
PC4824  SCD1U16V2KX-3GP  [C402H22]  142.02 117.33 270 bottom
PC4825  SCD1U50V3KX-GP  [C603H36]  131.48 136.98 270 top
PC4826  SC10U25V5KX-GP  [C805H56]  131.74 138.58 90 bottom
PC4838  SC560P50V-GP  [C603]  128.31 135.15 270 bottom
PC4901  SC1U25V3KX-1-GP  [C603H36]  62.82 17.35 90 top
PC4902  SCD01U50V2KX-1GP  [C402H22]  60.16 15.89 0 top
PC4903  SCD1U16V2KX-3GP  [C402H22]  59.27 15.89 0 top
PC4904  SC1U6D3V3KX-2GP  [C603H36]  60.38 23.91 0 bottom
PC4906  SCD1U16V2KX-3GP  [C402H22]  62.33 24.53 180 top
PC4909  SC4D7U25V5KX-GP  [C805H54]  66.53 21.11 180 bottom
PC4911  SC4D7U25V5KX-GP  [C805H54]  68.43 21.11 180 bottom
PC4912  SC10U25V5KX-GP  [C805H56]  64.62 21.11 180 bottom
PC4913  SCD1U50V3KX-GP  [C603H36]  68.18 21.11 180 top
PC4914  SC4D7U25V5KX-GP  [C805H54]  66.53 21.11 0 top
PC4915  SCD1U16V2KX-3GP  [C402H22]  54.21 18.83 270 top
PC4916  SC10U6D3V3MX-GP  [C603H38]  54.21 21.63 270 top
PC4917  SC10U6D3V3MX-GP  [C603H38]  54.21 20.23 270 top
PC4918  SCD22U10V2KX-1GP  [C402H22]  57.39 17.94 270 top
PC4919  SCD1U50V3KX-GP  [C603H36]  64.21 21.47 270 top
PC4920  SC4D7U6D3V3KX-GP  [C603H36]  77.42 16.88 0 top
PC4921  SCD1U16V2KX-3GP  [C402H22]  80.63 16.79 180 bottom
PC4922  SC330P50V2KX-3GP  [C402H22]  68.77 15.4 270 top
PC4923  SC22U6D3V5MX-2GP  [C805H58]  82.15 16.79 180 bottom
PC4924  SC22U6D3V5MX-2GP  [C805H58]  80.29 16.81 0 top
PC4925  SC22U6D3V5MX-2GP  [C805H58]  84.06 16.79 180 bottom
PC4926  SC22U6D3V5MX-2GP  [C805H58]  82.2 16.81 0 top
PC4927  SC22U6D3V5MX-2GP  [C805H58]  85.91 16.74 0 top
PC4928  SC22U6D3V5MX-2GP  [C805H58]  84.05 16.79 0 top
PC5102  SCD1U16V2KX-3GP  [C402H22]  149.08 99.31 270 bottom
PC5119  SC1U10V2KX-1GP  [C402H22]  148.62 103.79 90 bottom
PC5120  SC1U10V2KX-1GP  [C402H22]  145.9 103.88 90 bottom
PC8201  SCD1U16V2KX-3GP  [C402H22]  156.44 110.27 270 top
PC8202  SCD1U25V2KX-GP  [C402H22]  156.17 112.81 0 bottom
PC8203  SC1KP50V2KX-1GP  [C402H22]  157.14 103.85 90 bottom
PC8204  SCD01U50V2KX-1GP  [C402H22]  157.86 108 180 top
PC8205  SC47P50V2JN-3GP  [C402H22]  156.17 111.08 0 bottom
PC8206  SC330P50V2KX-3GP  [C402H22]  170.37 105.76 90 bottom
PC8207  SCD1U50V3KX-GP  [C603H36]  164.52 108.25 270 bottom
PC8208  SC4D7U25V5KX-GP  [C805H54]  165.69 98.4 180 top
PC8209  SC4D7U25V5KX-GP  [C805H54]  163.79 98.4 180 top
PC8210  SC10U25V5KX-GP  [C805H56]  165.69 98.4 0 bottom
PC8211  SCD1U50V3KX-GP  [C603H36]  163.56 105.53 0 bottom
PC8212  SC4D7U25V5KX-GP  [C805H54]  165.69 115.42 0 top
PC8213  SC4D7U25V5KX-GP  [C805H54]  163.79 115.42 0 top
PC8214  SC10U25V5KX-GP  [C805H56]  163.79 98.4 0 bottom
PC8215  SC10U25V5KX-GP  [C805H56]  165.69 115.42 180 bottom
PC8216  SCD1U50V3KX-GP  [C603H36]  162.3 112.77 180 bottom
PC8217  SC47P50V2JN-3GP  [C402H22]  157.44 112.43 90 bottom
PC8218  SC330P50V2KX-3GP  [C402H22]  170.39 107.54 90 bottom
PC8219  SC47P50V2JN-3GP  [C402H22]  158.31 111.62 90 bottom
PC8220  SCD1U25V2KX-GP  [C402H22]  167.09 98.27 180 bottom
PC8221  SCD1U25V2KX-GP  [C402H22]  167.09 115.54 0 bottom
PC8222  SC47P50V2JN-3GP  [C402H22]  159.21 112.43 270 bottom
PC8223  SC5600P50V2KX-GP-U  [C402-TO0D2H23]  156.73 109.36 90 top
PC8224  SC10U25V5KX-GP  [C805H56]  163.79 115.42 180 bottom
PC8225  SCD1U25V2KX-GP  [C402H22]  161.16 102.63 90 bottom
PC8226  SCD1U25V2KX-GP  [C402H22]  158.86 103.83 270 bottom
PC8302  SCD01U50V2KX-1GP  [C402H22]  173.51 56.52 90 top
PC8303  SC10U6D3V3MX-GP  [C603H38]  148.52 29.02 0 top
PC8307  SC10U6D3V3MX-GP  [C603H38]  155.08 38.07 0 top
PD4201  P6SBMJ27APT-GP  [D5436AKH97]  97.32 160.7 180 bottom
PD4203  LBAV99LT1G-1-GP  [SOT23-2D4-312H44]  128.43 174.22 90 top
PD4204  PESD24VS2UT-GP  [SOT-23-10H44]  118.05 169.57 270 top
PD4302  SMF18AT1G-GP  [SOD123FLAKH40]  149.03 173.05 180 top
PD4401  SD103AWS-1-GP  [SOD323AKH42]  113.91 162.39 180 bottom
PD4404  1N4148WS-7-F-GP  [SOD323AKH42]  115.08 173.93 0 top
PD4501  BZT52C15S-GP  [SOD323AKH42]  50.15 56.54 0 bottom
PD4502  BAT54SPT-1-GP  [SOT-23-13H51]  46.84 58.07 0 bottom
PD4503  BAT54SPT-1-GP  [SOT-23-13H51]  46.84 53.62 180 bottom
PG4402  GAP-CLOSE-PWR-3-GP  [GAP-CLOSE-PWR-3]  107.45 152.84 90 top
PG4403  GAP-CLOSE-PWR-3-GP  [GAP-CLOSE-PWR-3]  109.23 152.96 90 top
PG4404  GAP-CLOSE-PWR-3-GP  [GAP-CLOSE-PWR-3]  136.23 157.36 90 bottom
PG4405  GAP-CLOSE-PWR-3-GP  [GAP-CLOSE-PWR-3]  138.01 157.36 90 bottom
PG4407  GAP-CLOSE-PWR-3-GP  [GAP-CLOSE-PWR-3]  104.22 161.24 180 bottom
PG4408  GAP-CLOSE-PWR-3-GP  [GAP-CLOSE-PWR-3]  104.22 160.28 180 bottom
PG4409  GAP-CLOSE-PWR-3-GP  [GAP-CLOSE-PWR-3]  136.23 161.93 270 bottom
PG4410  GAP-CLOSE-PWR-3-GP  [GAP-CLOSE-PWR-3]  137.88 161.93 270 bottom
PG4411  GAP-CLOSE-PWR-3-GP  [GAP-CLOSE-PWR-3]  110.44 163.06 90 top
PG4412  -  [GAP-CLOSE-PWR]  118.78 155.76 90 bottom
PG4413  -  [GAP-CLOSE-PWR]  119.54 155.76 90 bottom
PG4414  -  [GAP-CLOSE-PWR]  118.02 155.76 90 bottom
PG4415  -  [GAP-CLOSE-PWR]  120.3 155.76 90 bottom
PG4517  -  [GAP-CLOSE-PWR]  34.93 27.33 270 bottom
PG4518  -  [GAP-CLOSE-PWR]  51.95 48.92 0 top
PG4519  -  [GAP-CLOSE-PWR]  45.35 27.11 90 bottom
PG4520  -  [GAP-CLOSE-PWR]  51.95 48.16 0 top
PG4521  -  [GAP-CLOSE-PWR]  32.11 50.55 90 top
PG4522  -  [GAP-CLOSE-PWR]  34.17 27.33 270 bottom
PG4523  -  [GAP-CLOSE-PWR]  44.59 27.11 90 bottom
PG4524  -  [GAP-CLOSE-PWR]  30.58 50.55 90 top
PG4525  -  [GAP-CLOSE-PWR]  31.34 50.55 90 top
PG4526  -  [GAP-CLOSE-PWR]  33.41 27.33 270 bottom
PG4527  -  [GAP-CLOSE-PWR]  43.83 27.11 90 bottom
PG4528  -  [GAP-CLOSE-PWR]  35.69 27.33 270 bottom
PG4529  -  [GAP-CLOSE-PWR]  36.46 27.33 270 bottom
PG4530  GAP-CLOSE-PWR-3-GP  [GAP-CLOSE-PWR-3]  50.02 60.99 270 bottom
PG4531  -  [GAP-CLOSE-PWR]  32.87 50.55 90 top
PG4532  GAP-CLOSE-PWR-3-GP  [GAP-CLOSE-PWR-3]  45.57 31.77 0 bottom
PG4533  -  [GAP-CLOSE-PWR]  43.07 27.11 90 bottom
PG4534  -  [GAP-CLOSE-PWR]  51.95 47.39 0 top
PG4535  GAP-CLOSE-PWR-3-GP  [GAP-CLOSE-PWR-3]  31.88 31.92 180 bottom
PG4536  -  [GAP-CLOSE-PWR]  51.95 51.2 0 top
PG4537  -  [GAP-CLOSE-PWR]  41.54 27.11 90 bottom
PG4538  -  [GAP-CLOSE-PWR]  42.3 27.11 90 bottom
PG4540  -  [GAP-CLOSE-PWR]  40.02 27.11 90 bottom
PG4541  -  [GAP-CLOSE-PWR]  46.88 27.11 90 bottom
PG4542  -  [GAP-CLOSE-PWR]  51.95 49.68 0 top
PG4543  -  [GAP-CLOSE-PWR]  51.95 50.44 0 top
PG4544  -  [GAP-CLOSE-PWR]  46.11 27.11 90 bottom
PG4545  -  [GAP-CLOSE-PWR]  40.78 27.11 90 bottom
PG4701  GAP-CLOSE-PWR-3-GP  [GAP-CLOSE-PWR-3]  117.08 121.19 90 bottom
PG4702  GAP-CLOSE-PWR-3-GP  [GAP-CLOSE-PWR-3]  116.95 116.36 270 bottom
PG4703  -  [GAP-CLOSE-PWR]  112.45 130.33 0 bottom
PG4704  -  [GAP-CLOSE-PWR]  112.45 131.09 0 bottom
PG4705  -  [GAP-CLOSE-PWR]  112.45 133.38 0 bottom
PG4706  -  [GAP-CLOSE-PWR]  112.45 134.14 0 bottom
PG4707  -  [GAP-CLOSE-PWR]  112.45 131.86 0 bottom
PG4708  -  [GAP-CLOSE-PWR]  112.45 132.62 0 bottom
PG4824  -  [GAP-CLOSE-PWR]  138.56 116.16 90 bottom
PG4825  -  [GAP-CLOSE-PWR]  137.8 116.16 90 bottom
PG4826  -  [GAP-CLOSE-PWR]  137.03 116.16 90 bottom
PG4827  -  [GAP-CLOSE-PWR]  135.67 136.73 0 top
PG4828  -  [GAP-CLOSE-PWR]  140.84 116.16 90 bottom
PG4830  -  [GAP-CLOSE-PWR]  140.08 116.16 90 bottom
PG4831  -  [GAP-CLOSE-PWR]  139.32 116.16 90 bottom
PG4832  GAP-CLOSE-PWR-3-GP  [GAP-CLOSE-PWR-3]  131.09 120.85 0 bottom
PG4834  -  [GAP-CLOSE-PWR]  135.67 137.49 0 top
PG4837  -  [GAP-CLOSE-PWR]  135.67 138.25 0 top
PG4838  -  [GAP-CLOSE-PWR]  135.67 139.02 0 top
PG4901  -  [GAP-CLOSE-PWR]  55.23 17.56 90 top
PG4902  -  [GAP-CLOSE-PWR]  55.99 17.56 90 top
PG4903  -  [GAP-CLOSE-PWR]  67.57 25.3 90 top
PG4904  -  [GAP-CLOSE-PWR]  66.81 25.3 90 top
PG4905  -  [GAP-CLOSE-PWR]  68.33 25.3 90 top
PG4906  -  [GAP-CLOSE-PWR]  66.05 25.3 90 top
PG4907  GAP-CLOSE-PWR-3-GP  [GAP-CLOSE-PWR-3]  85.07 17.68 180 bottom
PG4908  -  [GAP-CLOSE-PWR]  84.51 21.27 270 bottom
PG4909  -  [GAP-CLOSE-PWR]  83.75 21.27 270 bottom
PG4910  -  [GAP-CLOSE-PWR]  82.99 21.27 270 bottom
PG4911  -  [GAP-CLOSE-PWR]  82.23 21.27 270 bottom
PG4912  -  [GAP-CLOSE-PWR]  81.47 21.27 270 bottom
PG4913  -  [GAP-CLOSE-PWR]  80.7 21.27 270 bottom
PG4914  -  [GAP-CLOSE-PWR]  81.44 21.27 270 top
PG4915  -  [GAP-CLOSE-PWR]  82.2 21.27 270 top
PG4916  -  [GAP-CLOSE-PWR]  82.96 21.27 270 top
PG4917  -  [GAP-CLOSE-PWR]  83.73 21.27 270 top
PG4918  -  [GAP-CLOSE-PWR]  84.49 21.27 270 top
PG4919  -  [GAP-CLOSE-PWR]  80.68 21.27 270 top
PG4920  -  [GAP-CLOSE-PWR]  79.92 21.27 270 top
PG5105  -  [GAP-CLOSE-PWR]  146.31 105.03 90 bottom
PG8201  -  [GAP-CLOSE-PWR]  162.03 116.28 0 top
PG8202  -  [GAP-CLOSE-PWR]  162.03 117.04 0 top
PG8203  -  [GAP-CLOSE-PWR]  162.03 117.8 0 top
PG8204  -  [GAP-CLOSE-PWR]  162.03 118.57 0 top
PG8205  -  [GAP-CLOSE-PWR]  162.03 119.33 0 top
PG8206  -  [GAP-CLOSE-PWR]  162.03 120.09 0 top
PG8207  -  [GAP-CLOSE-PWR]  162.8 92.58 0 top
PG8208  -  [GAP-CLOSE-PWR]  162.8 93.34 0 top
PG8209  -  [GAP-CLOSE-PWR]  162.8 94.1 0 top
PG8210  -  [GAP-CLOSE-PWR]  162.8 94.87 0 top
PG8211  -  [GAP-CLOSE-PWR]  162.8 95.63 0 top
PG8212  -  [GAP-CLOSE-PWR]  162.8 96.39 0 top
PG8312  -  [GAP-CLOSE-PWR]  148.44 134.52 270 top
PG8313  -  [GAP-CLOSE-PWR]  150.89 141.3 90 top
PG8314  -  [GAP-CLOSE-PWR]  150.13 141.3 90 top
PG8315  -  [GAP-CLOSE-PWR]  151.66 141.3 90 top
PL4401  IND-5D6UH-45-GP  [L686647H119]  130.64 159.11 0 bottom
PL4501  IND-2D2UH-46-GP-U  [L736630-MH119]  45.35 40.41 180 bottom
PL4502  IND-3D3UH-57GP  [L736630H119]  35.82 40.28 0 bottom
PL4701  IND-D22UH-9-GP-U  [L115100-275300H158]  117.23 118.8 180 bottom
PL4801  IND-2D2UH-46-GP-U  [L736630-MH119]  132.11 129.57 180 bottom
PL4902  COIL-D68UH-5-GP  [L736630H119]  75.63 19.52 270 bottom
PL8201  IND-D33UH-7-GP  [L736630H119]  180.59 99.88 270 bottom
PL8202  IND-D33UH-7-GP  [L736630H119]  180.45 113.28 270 bottom
PQ4201  DMN5L06K-7-GP  [SOT23DGS2D4H48]  120.57 174.01 90 top
PQ4202  LMBT3904LT1G-GP  [SOT23CBE2D4H44]  124.44 173.82 90 top
PQ4204  PDTC124EU-1-GP  [SOT323CBE2D2H44]  92.34 155.73 90 bottom
PQ4205  PDTA124EU-1-GP  [SOT323CBE2D2H44]  92.9 158.81 90 bottom
PQ4206  2N7002K-2-GP  [SOT23DGS2D4H44]  88.5 155.81 180 bottom
PQ4401  2N7002KDW-GP  [SOT-363H44]  105.02 155.94 90 bottom
PQ4402  2N7002KDW-GP  [SOT-363H44]  105.29 164.6 270 top
PQ4408  2N7002KDW-GP  [SOT-363H44]  141.31 155.33 270 top
PQ4409  LMBT3906LT1G-1-GP  [SOT23CBE2D4H44]  112.25 175.59 180 top
PQ4410  2N7002KDW-GP  [SOT-363H44]  105.66 170 0 top
PQ4414  2N7002K-1-GP  [SOT23DGS2D4H44]  109.37 171.79 0 top
PQ8304  2N7002KDW-GP  [SOT-363H44]  171.19 53.98 180 top
PQ8305  2N7002KDW-GP  [SOT-363H44]  144.89 143.16 0 top
PQ8306  2N7002K-2-GP  [SOT23DGS2D4H44]  174.68 53.89 270 top
PQ8307  2N7002K-2-GP  [SOT23DGS2D4H44]  145.02 146.84 0 top
PQ8308  SIRA06DP-T1-GE3-GP  [PPAK-5PH45]  147.53 48.9 90 top
PR4202  15KR2F-GP  [R402H16]  126.8 172.47 180 top
PR4203  10KR2J-3-GP  [R402H16]  124.26 176.05 270 top
PR4204  2K2R2J-2-GP  [R402H16]  130.92 175.29 0 top
PR4205  33R2J-2-GP  [R402H16]  122.18 176.31 90 top
PR4206  33R2J-2-GP  [R402H16]  120.41 176.31 90 top
PR4207  240KR3-GP  [R603H22]  96.37 151.67 90 top
PR4208  47KR3J-L-GP  [R603H22]  98.2 149.05 0 top
PR4209  100KR2J-1-GP  [R402H16]  118.96 171.78 90 top
PR4210  -  [0R0402-PAD]  90.74 153.09 270 bottom
PR4214  3K3R6J-GP  [R1206H28]  88.65 158.81 90 bottom
PR4217  0R0603-PAD-1-GP-U  [0R0603-PAD-U]  103.15 169.39 0 top
PR4401  10KR2F-2-GP  [R402H16]  107.5 165.23 0 top
PR4402  D01R3721F-GP-U  [R3720H40]  108.34 150.68 90 top
PR4403  100KR2J-1-GP  [R402H16]  104.38 152.48 270 top
PR4404  3KR5J-GP  [R805H24]  105.06 162.08 270 top
PR4405  470KR2J-2-GP  [R402H16]  138.62 156.24 90 top
PR4406  0R2J-2-GP  [R402H16]  110.1 155.67 270 top
PR4407  309KR2F-GP  [R402H16]  105.16 158.2 270 bottom
PR4408  10R5J-GP  [R805H24]  115.07 158.58 0 bottom
PR4409  0R3J-0-U-GP  [R603H22]  111.92 162.84 0 top
PR4410  6D8R2F-GP  [R402H16]  125.34 167.6 0 top
PR4411  102KR2F-GP  [R402H16]  108.09 156.3 0 bottom
PR4413  169KR2F-1-GP  [R402H16]  109.23 160.23 180 top
PR4414  3D3MR2J-GP  [R402H16]  108.72 157.69 90 bottom
PR4416  D01R3721F-GP-U  [R3720H40]  137.12 159.64 270 bottom
PR4417  100KR2J-1-GP  [R402H16]  105.04 163.33 270 bottom
PR4418  -  [0R0402-PAD]  105.67 165.61 0 bottom
PR4419  100KR2J-1-GP  [R402H16]  110.27 154.08 270 bottom
PR4420  7D5R2F-GP  [R402H16]  108.59 165.13 0 bottom
PR4421  10R2F-L-GP  [R402H14]  109.48 165.13 0 bottom
PR4422  0R2J-2-GP  [R402H16]  104.91 159.19 90 bottom
PR4423  59KR2F-GP  [R402H16]  105.04 162.49 90 bottom
PR4424  8K45R2F-2-GP  [R402H16]  107.96 162.39 90 top
PR4425  2D2R5F-2-GP  [R805H24]  126.13 159.73 180 top
PR4426  -  [0R0402-PAD]  143.54 154.64 0 top
PR4427  78K7R2F-GP  [R402H16]  108.95 156.29 0 bottom
PR4428  100KR2J-1-GP  [R402H16]  111.56 154.52 180 bottom
PR4429  309KR2F-GP  [R402H16]  109.84 156.29 180 bottom
PR4430  100KR2J-1-GP  [R402H16]  111.51 156.29 0 bottom
PR4431  47KR2F-GP  [R402H16]  107.96 159.72 90 top
PR4432  120KR2F-L-GP  [R402H16]  110.5 157.69 270 bottom
PR4434  100KR2J-1-GP  [R402H16]  106.86 158.14 270 bottom
PR4435  10KR2F-2-GP  [R402H16]  103.97 164.6 0 bottom
PR4436  120KR2F-L-GP  [R402H16]  112.4 154.51 0 bottom
PR4437  160KR2F-GP  [R402H16]  112.91 156.82 270 bottom
PR4438  100KR2J-1-GP  [R402H16]  110.68 156.29 180 bottom
PR4439  10KR2F-2-GP  [R402H16]  104.81 165.59 180 bottom
PR4446  20KR2F-L-GP  [R402H16]  124.06 170.72 270 top
PR4448  0R2J-2-GP  [R402H16]  127.58 168.01 270 top
PR4452  0R2J-2-GP  [R402H16]  126.75 170.39 180 top
PR4454  10R2F-L-GP  [R402H14]  127.58 167.15 270 top
PR4464  680KR2J-GP  [R402H16]  104.07 166.73 90 top
PR4465  0R2J-2-GP  [R402H16]  107.53 174.56 180 top
PR4466  0R2J-2-GP  [R402H16]  106.62 173.52 180 top
PR4467  1MR2J-1-GP  [R402H16]  109.62 175.26 270 top
PR4468  0R2J-2-GP  [R402H16]  113.57 172.78 180 top
PR4469  100KR2J-1-GP  [R402H16]  109.63 174.41 90 top
PR4470  100KR2F-L1-GP  [R402H16]  106.59 172.25 270 top
PR4471  0R2J-2-GP  [R402H16]  112.71 172.78 0 top
PR4472  100KR2F-L1-GP  [R402H16]  112.64 167.62 90 top
PR4473  10KR2F-2-GP  [R402H16]  104.86 172.25 270 top
PR4474  100KR2J-1-GP  [R402H16]  112.21 169.74 180 top
PR4475  0R2J-2-GP  [R402H16]  103.56 167.57 270 top
PR4476  0R2J-2-GP  [R402H16]  102.95 165.23 180 top
PR4501  0R2J-2-GP  [R402H16]  36.3 59.97 270 top
PR4504  -  [0R0402-PAD]  45.57 59.2 0 top
PR4506  -  [0R0402-PAD]  37.09 56.41 90 top
PR4507  -  [0R0402-PAD]  36.84 57.68 180 top
PR4512  6K8R2F-2-GP  [R402H16]  39 59.94 0 top
PR4517  88K7R2F-GP  [R402H16]  37.73 57.68 180 top
PR4523  10KR2F-2-GP  [R402H16]  39.86 59.08 180 top
PR4524  1D5R3-GP  [R603H22]  46.46 53.62 90 top
PR4525  0R2J-2-GP  [R402H16]  43.8 59.2 0 top
PR4526  9K76R2F-1-GP  [R402H16]  42.53 60.55 90 top
PR4527  15K4R2F-GP  [R402H16]  42.53 59.59 270 top
PR4528  1D5R3-GP  [R603H22]  36.3 53.11 90 top
PR4529  2D2R5F-2-GP  [R805H24]  42.21 41.53 180 top
PR4530  0R2J-2-GP  [R402H16]  36.3 59.08 90 top
PR4531  115KR2F-GP  [R402H16]  44.69 59.2 180 top
PR4532  -  [0R0402-PAD]  41.39 58.56 90 bottom
PR4533  2D2R5F-2-GP  [R805H24]  40.38 41.53 180 top
PR4534  100KR2J-1-GP  [R402H16]  37.09 55.52 90 top
PR4535  0R2J-2-GP  [R402H16]  38.49 61.21 270 top
PR4601  75R2F-2-GP  [R402H16]  121.81 140.56 270 top
PR4602  499R2F-2-GP  [R402H16]  116.88 145.83 270 top
PR4603  1K27R2F-L-GP  [R402H16]  113.12 143.55 270 top
PR4604  10R2F-L-GP  [R402H14]  112.55 142.3 0 top
PR4606  0R2J-2-GP  [R402H16]  113.12 144.38 270 top
PR4607  124KR2F-GP  [R402H16]  114.44 135.96 180 top
PR4610  100KR2F-L1-GP  [R402H16]  117.49 142.94 0 bottom
PR4613  5K1R2F-2-GP  [R402H16]  114.69 142.94 180 bottom
PR4614  90K9R2F-GP  [R402H16]  121.81 137.89 270 top
PR4615  3K83R2F-GP  [R402H16]  115.55 145.83 0 top
PR4616  -  [0R0402-PAD]  121.81 142.34 90 top
PR4617  15KR2F-GP  [R402H16]  114.66 145.83 0 top
PR4618  -  [0R0402-PAD]  121.81 141.45 90 top
PR4619  -  [0R0402-PAD]  121.81 138.78 90 top
PR4620  54D9R2F-L1-GP  [R402H16]  121.81 143.23 90 top
PR4621  -  [0R0402-PAD]  121.61 144.25 90 top
PR4622  NTC-470K-5-GP-U  [NTC-402H22-U]  124.44 128.55 180 bottom
PR4624  -  [0R0402-PAD]  116.88 144.94 270 top
PR4628  -  [0R0402-PAD]  118.66 144.94 90 top
PR4630  130R2F-1-GP  [R402H16]  121.81 139.67 90 top
PR4701  0R0603-PAD-1-GP-U  [0R0603-PAD-U]  116.85 136.34 0 top
PR4702  3K65R2F-1-GP  [R402H16]  112.25 136.68 90 top
PR4703  4K42R2F-GP  [R402H16]  112.25 135.79 270 top
PR4704  NTC-10K-26-GP-U  [NTC-402H22-U]  111.15 119.39 180 bottom
PR4705  340R2F-GP  [R402H16]  112.12 140.16 90 top
PR4706  0R2J-2-GP  [R402H16]  112.11 141.02 90 top
PR4707  10MR2F-GP  [R402H16]  113.52 138.94 0 top
PR4708  11KR2F-L-GP  [R402H16]  112.25 137.6 270 top
PR4817  133KR2F-GP  [R402H16]  134.05 146.45 270 top
PR4819  -  [0R0402-PAD]  131.79 147.47 270 top
PR4820  2D2R3-1-U-GP  [R603H22]  133.56 140.16 270 top
PR4821  -  [0R0402-PAD]  134.03 145.35 90 top
PR4822  10KR2F-2-GP  [R402H16]  126.99 147.47 0 top
PR4823  21KR2F-GP  [R402H16]  127.42 146.2 270 top
PR4824  470KR2F-GP  [R402H16]  127.42 145.34 270 top
PR4837  2D2R5F-2-GP  [R805H24]  127.29 133 0 bottom
PR4901  31K6R2F-GP  [R402H16]  61.05 15.89 0 top
PR4902  133KR2F-GP  [R402H16]  58.52 25.12 180 top
PR4903  10KR2F-2-GP  [R402H16]  59.78 17.16 90 top
PR4904  20KR2F-L-GP  [R402H16]  56.37 24.54 90 top
PR4905  2D2R3-1-U-GP  [R603H22]  64.21 22.86 90 top
PR4906  -  [0R0402-PAD]  60.54 14.62 270 top
PR4907  -  [0R0402-PAD]  63.19 24.53 0 top
PR4908  1KR2F-3-GP  [R402H16]  57.7 25.11 0 top
PR4909  -  [0R0402-PAD]  60.38 25.16 180 top
PR4910  0R2J-2-GP  [R402H16]  61.2 25.18 180 top
PR4911  0R0603-PAD-1-GP-U  [0R0603-PAD-U]  58.02 16.03 0 top
PR4912  2D2R5F-2-GP  [R805H24]  72.07 15.4 270 top
PR5110  -  [0R0402-PAD]  147.3 99.31 270 bottom
PR8201  499KR2F-1-GP  [R402H16]  156.55 109.78 270 bottom
PR8202  2D2R2F-GP  [R402H16]  156.22 114.53 180 bottom
PR8203  100KR2J-1-GP  [R402H16]  161.14 114.84 180 bottom
PR8206  7K5R2F-1-GP  [R402H16]  155.56 108.36 90 bottom
PR8207  -  [0R0402-PAD]  156.42 104.68 270 bottom
PR8208  0R2J-2-GP  [R402H16]  156.9 107.13 0 bottom
PR8209  7K87R2F-GP  [R402H16]  157.01 108.01 180 top
PR8210  0R0603-PAD-1-GP-U  [0R0603-PAD-U]  161.4 103.76 270 bottom
PR8211  0R0603-PAD-1-GP-U  [0R0603-PAD-U]  161.02 112.77 0 bottom
PR8212  100R2F-L1-GP-U  [R402H14]  159.21 113.26 90 bottom
PR8213  100R2F-L1-GP-U  [R402H14]  157.44 113.26 90 bottom
PR8215  2D2R5F-2-GP  [R805H24]  173.95 107.54 90 bottom
PR8216  2D2R5F-2-GP  [R805H24]  173.95 105.64 90 bottom
PR8220  -  [0R0402-PAD]  157.94 114.53 0 bottom
PR8221  -  [0R0402-PAD]  158.83 114.53 0 bottom
PR8222  27KR2F-L-GP  [R402H16]  155.53 106.35 0 bottom
PR8223  2D2R3J-2-GP  [R603H22]  164.52 109.55 90 bottom
PR8224  10K7R2F-GP  [R402H16]  164.17 107.16 270 bottom
PR8256  1KR2J-1-GP  [R402H16]  160.59 101.25 0 bottom
PR8257  -  [0R0402-PAD]  157.59 102.56 0 bottom
PR8258  10KR2J-3-GP  [R402H16]  158.48 102.56 0 bottom
PR8259  10KR2J-3-GP  [R402H16]  159.37 102.56 180 bottom
PR8260  13KR2F-GP  [R402H16]  161.42 101.25 0 bottom
PR8301  1KR2J-1-GP  [R402H16]  142.96 137.78 90 top
PR8310  100KR2J-1-GP  [R402H16]  170.26 56.8 180 top
PR8311  100KR2J-1-GP  [R402H16]  170.57 51.62 90 top
PR8312  1MR2J-1-GP  [R402H16]  169.43 57.05 180 top
PR8313  100KR2J-1-GP  [R402H16]  142.9 144.1 0 top
PR8314  100KR2J-1-GP  [R402H16]  172.35 51.62 270 top
PR8315  10R2J-2-GP  [R402H14]  175.24 56.67 90 top
PR8316  10R2J-2-GP  [R402H14]  149.21 144.17 270 top
PR8317  10R2J-2-GP  [R402H14]  147.23 147.87 0 top
PT4501  SE220U6D3VM-38-GP  [SE361414H178]  46.08 31.77 270 bottom
PT4502  SE220U6D3VM-38-GP  [SE361414H178]  31.38 31.92 90 bottom
PT4701  SE330U2D5VM-8-GP  [SE361416H178]  102.34 116.49 90 bottom
PT4702  SE33U25VM-10-GP  [SE361413H182]  106.45 129.42 180 bottom
PT4803  SE330U2D5VM-14-GP  [SE361414H178]  130.58 120.96 90 bottom
PT8206  SE330U2D5VM-14-GP  [SE361414H178]  190.23 111.38 270 bottom
PT8207  SE330U2D5VM-14-GP  [SE361414H178]  190.23 103.5 270 bottom
PT8208  SE330U2D5VM-14-GP  [SE361414H178]  190.23 95.63 270 bottom
PU4201  SI7121DN-T1-GE3-GP  [PPAK-8P-2H45]  101.07 154.21 270 top
PU4401  HPA02224RGRR-1-GP  [QFN20G3D5-G2D15H40]  109.86 161.5 0 bottom
PU4402  SI7121DN-T1-GE3-GP  [PPAK-8P-2H45]  101.84 149.76 90 top
PU4403  SI7121DN-T1-GE3-GP  [PPAK-8P-2H45]  135.54 159.28 0 top
PU4405  SIS412DN-T1-GE3-GP  [PPAK-8P-2H45]  122.71 157.56 270 bottom
PU4406  SIS412DN-T1-GE3-GP  [PPAK-8P-2H45]  124.24 162.13 90 bottom
PU4407  INA199A1-GP  [SC70-6H44]  123.12 168.71 270 top
PU4501  SIS412DN-T1-GE3-GP  [PPAK-8P-2H45]  49.92 44.98 0 top
PU4502  SIS780DN-T1-GE3-GP  [PPAK-8P-2H45]  45.35 43.46 180 top
PU4503  TPS51225RUKR-GP  [QFN20-G1D75H32]  41.54 55.14 0 top
PU4504  SIS412DN-T1-GE3-GP  [PPAK-8P-2H45]  32.52 44.98 0 top
PU4505  SIS412DN-T1-GE3-GP  [PPAK-8P-2H45]  37.09 43.46 180 top
PU4601  ISL95813HRZ-GP  [QFN20G4030-G275175H40]  117.03 141.13 0 top
PU4701  FDMS3600-02-RJK0215-COLAY-GP  [PPAK-8P-G5324H44-COLAY]  117.79 128.78 90 bottom
PU4805  SIS412DN-T1-GE3-GP  [PPAK-8P-2H45]  129.2 132.74 180 top
PU4806  RT8237CZQW-2-GP  [DFN10G3-G265175H32]  130.34 144.35 0 top
PU4808  SIS412DN-T1-GE3-GP  [PPAK-8P-2H45]  133.64 134.27 0 top
PU4901  TPS51716RUKR-GP  [QFN20-G1D75H32]  59.54 20.98 90 top
PU4902  SIS412DN-T1-GE3-GP  [PPAK-8P-2H45]  70.85 23.14 90 top
PU4903  SIS780DN-T1-GE3-GP  [PPAK-8P-2H45]  72.37 18.57 270 top
PU5101  S-1339D15-M5001-GP  [SOT-23-5H52]  147.68 101.59 270 bottom
PU8201  RT8812AGQW-GP  [QFN20-G1D75H32]  159.98 108.05 0 bottom
PU8202  SIRA14DP-T1-GE3-GP  [PPAK-5PH45]  170.64 94.97 90 top
PU8203  SIRA12DP-T1-GE3-GP  [PPAK-5PH45]  172.68 101.45 270 top
PU8204  SIRA14DP-T1-GE3-GP  [PPAK-5PH45]  170.64 94.97 270 bottom
PU8205  SIRA12DP-T1-GE3-GP  [PPAK-5PH45]  172.68 101.45 90 bottom
PU8206  SIRA14DP-T1-GE3-GP  [PPAK-5PH45]  170.64 118.21 90 top
PU8207  SIRA12DP-T1-GE3-GP  [PPAK-5PH45]  172.68 111.73 270 top
PU8208  SIRA14DP-T1-GE3-GP  [PPAK-5PH45]  170.64 118.21 270 bottom
PU8209  SIRA12DP-T1-GE3-GP  [PPAK-5PH45]  172.68 111.73 90 bottom
PWR1  ETY-CON4-34-GP  [6916K-Q04M-00L]  199.1 165.67 0 top
Q1201  DMN5L06K-7-GP  [SOT23DGS2D4H48]  89.45 13.96 270 top
Q1202  2N7002K-2-GP  [SOT23DGS2D4H44]  89.45 17.64 90 top
Q1701  2N7002KDW-GP  [SOT-363H44]  155.51 46.21 90 bottom
Q1801  2N7002KDW-GP  [SOT-363H44]  154.63 69.43 270 bottom
Q1901  2N7002K-2-GP  [SOT23DGS2D4H44]  146.21 61.14 90 top
Q2401  2N7002K-2-GP  [SOT23DGS2D4H44]  173.6 71.83 90 bottom
Q2402  DMP2130L-7-GP  [SOT23DGS2D4H48]  167.62 78.26 270 top
Q2403  2N7002K-2-GP  [SOT23DGS2D4H44]  167.62 74.58 270 top
Q2404  LMBT3906LT1G-1-GP  [SOT23CBE2D4H44]  167.6 70.92 90 top
Q2505  2N7002K-2-GP  [SOT23DGS2D4H44]  34.27 11.59 270 top
Q2601  2N7002KDW-GP  [SOT-363H44]  126.97 116.17 90 top
Q2602  2N7002K-2-GP  [SOT23DGS2D4H44]  162.08 67.67 270 top
Q2603  LMBT3904LT1G-GP  [SOT23CBE2D4H44]  52.55 64.72 180 bottom
Q3001  2N7002K-2-GP  [SOT23DGS2D4H44]  61.75 169.83 0 top
Q3002  LMBT3904LT1G-GP  [SOT23CBE2D4H44]  49.54 163.91 270 top
Q3003  LMBT3904LT1G-GP  [SOT23CBE2D4H44]  57.71 165.83 90 top
Q3004  DMP2130L-7-GP  [SOT23DGS2D4H48]  58.05 172.01 90 top
Q3601  2N7002KDW-GP  [SOT-363H44]  30.86 18.29 90 top
Q3602  MMBT2222A-3-GP  [SOT23CBE2D4H44]  167.62 67.21 270 top
Q5401  LMBT3904LT1G-GP  [SOT23CBE2D4H44]  27.87 78.74 270 bottom
Q5402  2N7002KDW-GP  [SOT-363H44]  33.51 78.9 90 bottom
Q5403  2N7002K-2-GP  [SOT23DGS2D4H44]  27.79 78.64 180 top
Q6101  DDTA144VCA-7-F-GP  [SOT23CBE2D4H44]  31.1 6.89 180 top
Q6102  DDTA144VCA-7-F-GP  [SOT23CBE2D4H44]  34.91 6.89 180 top
Q6103  2N7002K-2-GP  [SOT23DGS2D4H44]  44.18 6.13 0 top
Q6104  DDTA144VCA-7-F-GP  [SOT23CBE2D4H44]  38.48 6.88 180 top
Q6105  2N7002K-2-GP  [SOT23DGS2D4H44]  40 10.74 90 top
Q6201  DDTA144VCA-7-F-GP  [SOT23CBE2D4H44]  195.52 115.09 0 top
Q6202  DMN3404L-7-GP  [SOT23DGS2D4H48]  187.67 126.93 270 top
Q6203  DMP2130L-7-GP  [SOT23DGS2D4H48]  47.86 78.43 270 top
Q6204  2N7002KDW-GP  [SOT-363H44]  53.61 74.41 270 top
Q6205  2N7002K-2-GP  [SOT23DGS2D4H44]  45.15 70.66 180 top
Q7301  2N7002K-2-GP  [SOT23DGS2D4H44]  148.7 127.92 0 bottom
Q7601  2N7002KDW-GP  [SOT-363H44]  199.37 138.74 90 top
Q7602  2N7002KDW-GP  [SOT-363H44]  194.72 124.06 270 bottom
Q7606  2N7002K-2-GP  [SOT23DGS2D4H44]  191 122.65 270 bottom
Q8301  2N7002K-2-GP  [SOT23DGS2D4H44]  143.62 129.95 0 top
Q8302  DMP2130L-7-GP  [SOT23DGS2D4H48]  143.21 135.49 0 top
R401  62R2J-GP  [R402H16]  91.83 88.99 270 bottom
R402  51R2J-2-GP  [R402H16]  100.31 94.14 180 top
R403  56R2J-4-GP  [R402H16]  93.6 88.86 270 bottom
R404  -  [0R0402-PAD]  131.81 60.99 180 bottom
R405  10KR2J-3-GP  [R402H16]  92.88 96.89 90 bottom
R406  51R2J-2-GP  [R402H16]  99.42 94.14 180 top
R407  200R2F-L-GP  [R402H16]  105.5 79.79 270 top
R408  121R2F-GP  [R402H16]  102.86 74.47 270 top
R409  100R2F-L1-GP-U  [R402H14]  102.87 73.53 270 top
R410  470R2J-2-GP  [R402H16]  132.7 62.01 0 bottom
R411  0R2J-2-GP  [R402H16]  92.72 98.61 270 bottom
R601  49D9R2F-GP  [R402H16]  91.4 85.99 270 bottom
R602  49D9R2F-GP  [R402H16]  130.24 63.73 180 bottom
R603  8K2R2F-1-GP  [R402H16]  130.93 99.94 180 bottom
R604  1KR2J-1-GP  [R402H16]  91.41 85.03 90 bottom
R605  1KR2J-1-GP  [R402H16]  91.41 84.21 90 bottom
R606  49D9R2F-GP  [R402H16]  124.21 84.71 180 top
R701  43R2J-GP  [R402H16]  93.55 86.97 270 bottom
R702  100R2F-L1-GP-U  [R402H14]  93.86 94.17 270 bottom
R703  75R2F-2-GP  [R402H16]  91.81 86.86 270 bottom
R704  130R2F-1-GP  [R402H16]  91.83 88.16 270 bottom
R705  150R2J-L1-GP-U  [R402H16]  88.31 88.94 270 bottom
R706  10KR2J-3-GP  [R402H16]  98.89 100.61 180 bottom
R707  100KR2F-L1-GP  [R402H16]  100.55 99.36 90 top
R709  47KR2F-GP  [R402H16]  97.58 99.34 90 bottom
R710  10KR2J-3-GP  [R402H16]  96.07 100.63 180 bottom
R711  0R0603-PAD-1-GP-U  [0R0603-PAD-U]  122.49 84.31 180 top
R712  47KR2F-GP  [R402H16]  95.68 98.47 90 bottom
R713  100KR2F-L1-GP  [R402H16]  95.18 100.63 180 bottom
R801  24D9R2F-L-GP  [R402H16]  123.83 92.82 180 top
R901  100R2F-L1-GP-U  [R402H14]  93.86 92.39 90 bottom
R1101  0R0805-PAD-1-GP-U  [0R0805-PAD-U]  139.55 105.97 0 top
R1102  0R0603-PAD-1-GP-U  [0R0603-PAD-U]  127.72 110.18 270 top
R1103  0R0603-PAD-1-GP-U  [0R0603-PAD-U]  154.98 72.78 180 bottom
R1104  0R0603-PAD-1-GP-U  [0R0603-PAD-U]  124.09 82.17 0 top
R1105  0R0805-PAD-1-GP-U  [0R0805-PAD-U]  132.51 109.39 90 top
R1201  -  [0R0402-PAD]  120.56 38.15 0 top
